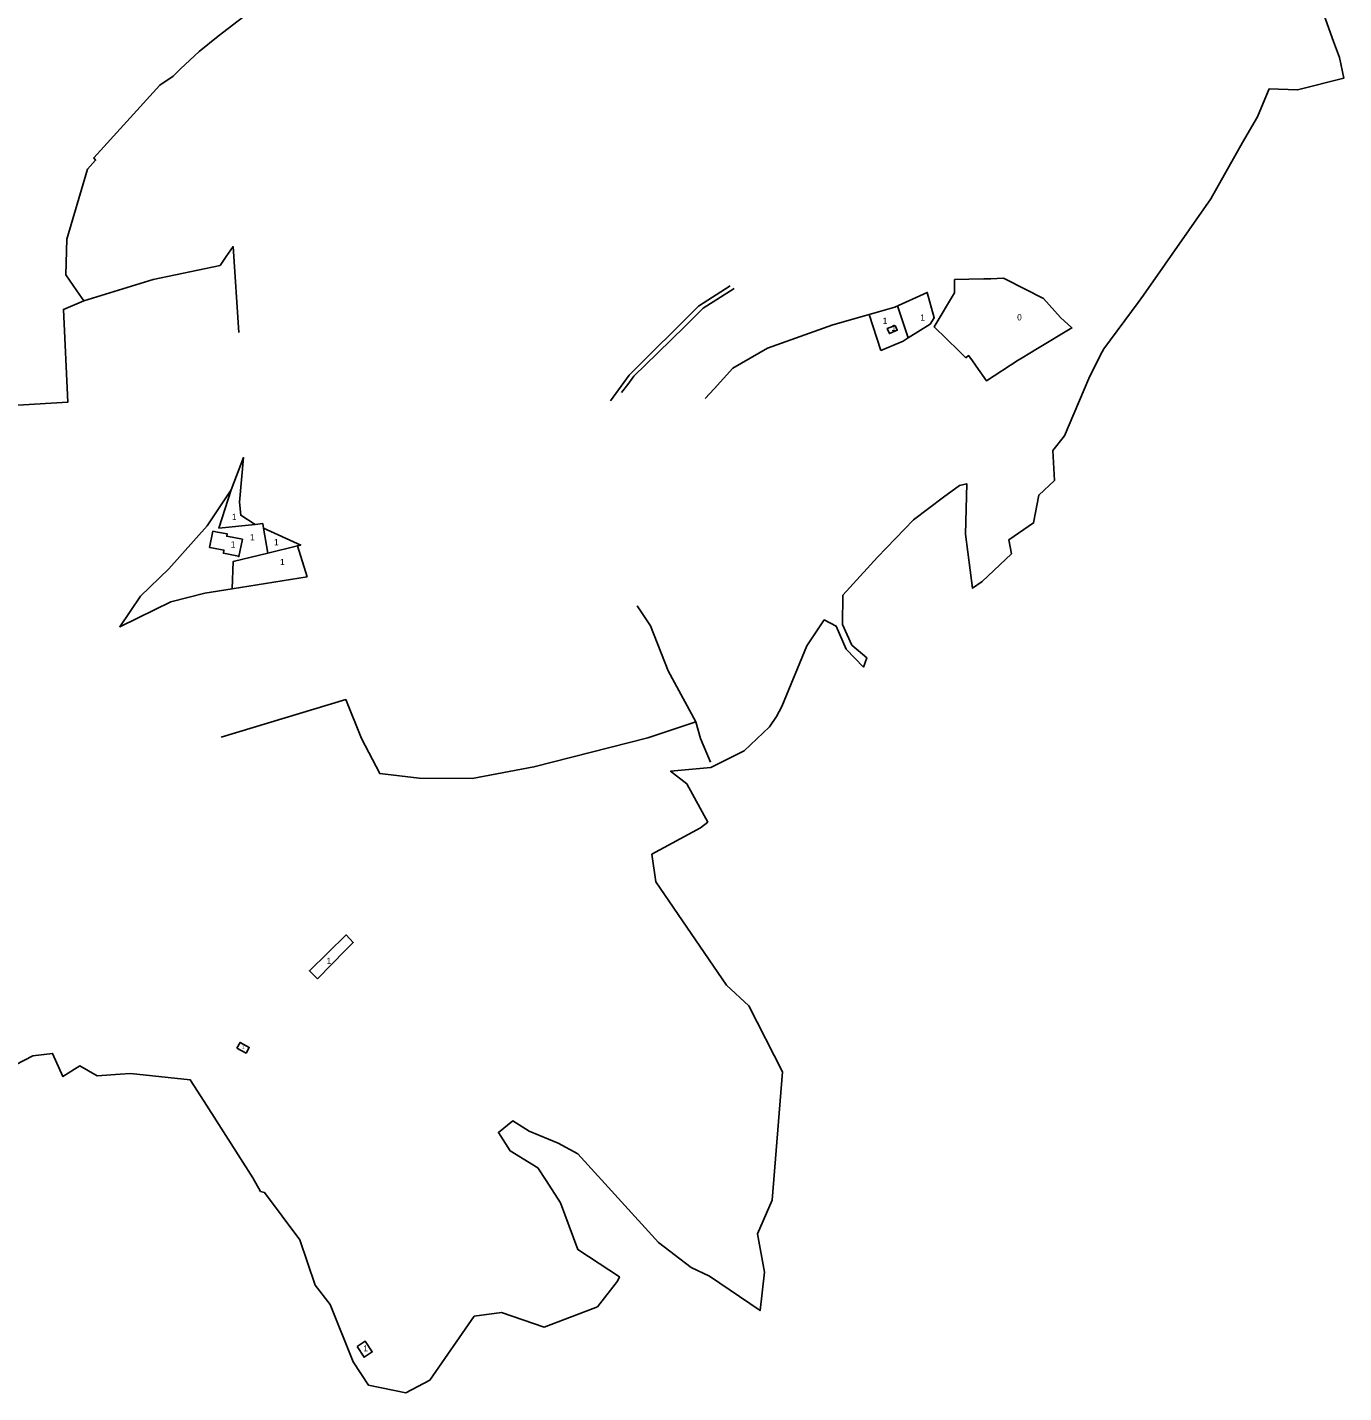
# Model space of a CAD drawing. Extents: x -494856 to -492815, y -1145343 to -1142968.
# Drawn here: x -494018 to -493180, y -1145025 to -1144155 of the extents above; entities that cross this region are included whole.
import ezdxf

# ---------------------------------------------------------------- set-up
doc = ezdxf.new("R2010")
doc.units = 0
for name, color, linetype in [('Level 255', 7, 'Continuous'), ('NERES_POP', 7, 'Continuous'), ('NERES_SET', 7, 'Continuous'), ('OVNE_POP', 7, 'Continuous'), ('OVNE_SET', 7, 'Continuous'), ('OVNI_SET', 7, 'Continuous'), ('POR_SET', 7, 'Continuous')]:
    doc.layers.add(name, color=color, linetype=linetype)

msp = doc.modelspace()

# ---------------------------------------------------------------- linework, layer by layer
at = {"layer": 'NERES_SET'}
for p, q in [((-493463.77, -1144332.66), (-493456.96, -1144353)), ((-493864.59, -1144489.99), (-493867.31, -1144474.24))]:
    msp.add_line(p, q, dxfattribs=at)
for points in [[(-493474.34, -1144361.13), (-493460.19, -1144355.01), (-493456.96, -1144353), (-493442.97, -1144344.29), (-493440.37, -1144340.24), (-493444.77, -1144324.08), (-493465.36, -1144333.38), (-493481.68, -1144338.07), (-493474.34, -1144361.13)], [(-493465.16, -1144345.03), (-493470.21, -1144347.11), (-493468.93, -1144350.26), (-493463.87, -1144348.17), (-493465.16, -1144345.03)], [(-493839.51, -1144505.25), (-493845.75, -1144485.41), (-493843.66, -1144484.9), (-493867.31, -1144474.24), (-493867.82, -1144471.29), (-493872.77, -1144471.82), (-493881.83, -1144465.91), (-493882.75, -1144457.66), (-493880.08, -1144429.23), (-493887.98, -1144449.69), (-493903.17, -1144472.68), (-493927.68, -1144500.06), (-493945.66, -1144517.42), (-493958.85, -1144536.9), (-493947.2, -1144531.21), (-493926.34, -1144521.03), (-493904.68, -1144515.59), (-493887.28, -1144512.83), (-493839.51, -1144505.25)], [(-493887.98, -1144449.69), (-493895.75, -1144474.27), (-493872.77, -1144471.82)], [(-493880.84, -1144481.11), (-493890.74, -1144479.29), (-493890.44, -1144477.86), (-493896.76, -1144476.63), (-493899.54, -1144476.09), (-493901.66, -1144486.4), (-493899.21, -1144486.86), (-493892.53, -1144488.11), (-493892.84, -1144490.14), (-493883.3, -1144491.99), (-493883.32, -1144492.24), (-493883.07, -1144492.28), (-493880.84, -1144481.11)], [(-493887.28, -1144512.83), (-493886.66, -1144495.37), (-493864.59, -1144489.99), (-493845.75, -1144485.41)], [(-493833.05, -1144761.18), (-493815.06, -1144742.79), (-493810.27, -1144737.9), (-493814.82, -1144733.12), (-493838.14, -1144755.98), (-493833.05, -1144761.18)], [(-493884.3, -1144805.21), (-493882.32, -1144801.59), (-493876.46, -1144804.8), (-493878.45, -1144808.42), (-493884.3, -1144805.21)], [(-493807.73, -1144995.25), (-493802.55, -1144991.88), (-493798.16, -1144998.63), (-493803.34, -1145002), (-493807.73, -1144995.25)]]:
    msp.add_lwpolyline(points, dxfattribs=at)
at = {"layer": 'OVNE_SET'}
for points in [[(-493391.26, -1144490.58), (-493392.81, -1144481.56), (-493377.07, -1144470.82), (-493373.77, -1144453.1), (-493363.72, -1144443.72), (-493364.89, -1144424.71), (-493357.31, -1144415.43), (-493342, -1144378.84), (-493334.48, -1144363.83), (-493332.27, -1144360.08), (-493310.53, -1144330.59), (-493307.09, -1144325.92), (-493264.2, -1144264.49), (-493244.07, -1144228.61), (-493234.47, -1144212.27), (-493232.98, -1144208.63), (-493227.2, -1144194.53), (-493208.99, -1144195.14), (-493179.67, -1144187.67), (-493182.31, -1144174.57), (-493186.18, -1144164.23), (-493200.41, -1144124.33)], [(-493877.18, -1144146.31), (-493896.2, -1144160.96), (-493908.35, -1144170.77), (-493920.3, -1144181.64), (-493922.82, -1144184.17), (-493924.92, -1144186.28), (-493933.37, -1144192.19), (-493975.39, -1144238.44), (-493974.24, -1144239.92), (-493979.36, -1144245.52), (-493992.48, -1144290.17), (-493993.27, -1144312.87), (-493986.15, -1144323.12), (-493981.79, -1144329.39), (-493994.7, -1144334.94), (-493991.9, -1144393.92), (-494126.29, -1144401.94)], [(-494025.28, -1144815.77), (-494014.28, -1144810.1), (-494001.7, -1144808.56), (-493995.06, -1144823.33), (-493984.26, -1144816.54), (-493973.23, -1144822.9), (-493958.68, -1144821.91), (-493952.03, -1144821.46), (-493913.99, -1144825.36), (-493905.1, -1144839.3), (-493874.16, -1144887.84), (-493869.23, -1144896.41), (-493866.63, -1144897.15), (-493844.28, -1144927.36), (-493834.46, -1144956.07), (-493824.92, -1144968.44), (-493810.2, -1145005.04), (-493800.47, -1145019.83), (-493776.76, -1145024.61), (-493761.56, -1145016.66), (-493733.22, -1144975.99), (-493715.89, -1144973.59), (-493709.06, -1144975.94), (-493688.67, -1144982.93), (-493654.74, -1144970.03), (-493642.02, -1144953.58), (-493640.81, -1144950.84), (-493667.28, -1144933.48), (-493678.27, -1144903.8), (-493687.35, -1144889.42), (-493692.79, -1144881.47), (-493710.23, -1144870.65), (-493717.8, -1144858.9), (-493708.61, -1144851.52), (-493698.31, -1144858.14), (-493679.79, -1144865.64), (-493667.32, -1144872.56), (-493615.82, -1144929.02), (-493595.09, -1144944.89), (-493583.38, -1144950.39), (-493551.22, -1144972.37), (-493548.51, -1144947.81), (-493552.96, -1144923.5), (-493543.6, -1144902.02), (-493536.9, -1144820.34), (-493558.41, -1144778.35), (-493572.68, -1144765.06), (-493617.52, -1144699.37), (-493620.13, -1144681.68), (-493589.17, -1144664.99), (-493584.49, -1144661.27), (-493597.81, -1144636.97), (-493608.17, -1144628.95), (-493582.62, -1144626.63), (-493561.44, -1144615.93), (-493545.19, -1144600.7), (-493540.78, -1144594.03), (-493537.34, -1144587.82), (-493521.42, -1144549.12), (-493510.35, -1144532.58), (-493502.68, -1144536.5), (-493496.46, -1144551.15), (-493485.41, -1144562.58), (-493483.33, -1144556.66), (-493492.87, -1144548.65), (-493498.78, -1144535.49), (-493498.53, -1144516.78), (-493476.41, -1144492.57), (-493453.56, -1144468.76), (-493434.4, -1144454.46), (-493424.3, -1144446.92)], [(-493424.3, -1144446.92), (-493419.69, -1144445.89), (-493420.39, -1144477.98), (-493416.08, -1144512.29), (-493409.91, -1144508.07), (-493391.26, -1144490.58)]]:
    msp.add_lwpolyline(points, dxfattribs=at)
at = {"layer": 'OVNI_SET'}
msp.add_lwpolyline([(-493427.45, -1144315.87), (-493427.44, -1144324.29), (-493440.48, -1144346.07), (-493424.77, -1144361.31), (-493420.27, -1144365.67), (-493418.49, -1144364.31), (-493416.44, -1144367.08), (-493413.62, -1144370.97), (-493407.07, -1144380.45), (-493386.95, -1144367.31), (-493384.27, -1144365.66), (-493374.56, -1144359.77), (-493352.68, -1144346.72), (-493359.86, -1144339.98), (-493370.83, -1144327.89), (-493395.02, -1144315.68), (-493396.31, -1144315.03), (-493400.38, -1144315.19), (-493404.24, -1144315.35), (-493408.68, -1144315.46), (-493418.29, -1144315.69), (-493427.45, -1144315.87)], dxfattribs=at)
at = {"layer": 'POR_SET'}
for points in [[(-493883.18, -1144349.61), (-493886.74, -1144294.91), (-493891.07, -1144301.17)], [(-493981.79, -1144329.39), (-493937.68, -1144315.8), (-493895.05, -1144306.93), (-493891.07, -1144301.17)], [(-493646.45, -1144393.19), (-493634.56, -1144376.68), (-493590.51, -1144332.9), (-493570.17, -1144319.8)], [(-493567.8, -1144321.52), (-493587.4, -1144334.19), (-493598.97, -1144345.5), (-493616.55, -1144362.69), (-493631.63, -1144377.43), (-493635.52, -1144382.6), (-493639.39, -1144387.76)], [(-493481.68, -1144338.07), (-493484.68, -1144338.93), (-493504.9, -1144344.75), (-493546.52, -1144359.6), (-493568.61, -1144372.37), (-493580.56, -1144385.46), (-493586.22, -1144391.66)], [(-493894.26, -1144607.28), (-493814.96, -1144583.26), (-493805.03, -1144608.19), (-493793.38, -1144630.42), (-493768.29, -1144633.3), (-493734.57, -1144633.63), (-493695.2, -1144626.18), (-493622.69, -1144607.7), (-493592.17, -1144597.43), (-493609.77, -1144564.99), (-493621.07, -1144536.32), (-493629.49, -1144523.7)], [(-493582.88, -1144623.14), (-493589.14, -1144608.02), (-493592.17, -1144597.43)]]:
    msp.add_lwpolyline(points, dxfattribs=at)

# ---------------------------------------------------------------- texts
at = {"layer": 'Level 255'}
for height, p in [(4, (-493827.2, -1144751.7)), (2, (-493881.05, -1144805.55)), (4, (-493803.87, -1144998.36))]:
    msp.add_text('1', height=height, dxfattribs=at).set_placement(p)
at = {"layer": 'NERES_POP'}
for p in [(-493449.24, -1144342.01), (-493473.19, -1144344.13), (-493467.58, -1144348.53), (-493887.5, -1144468.97), (-493876.01, -1144481.95), (-493888.23, -1144486.52), (-493860.69, -1144485.04), (-493856.86, -1144497.72)]:
    msp.add_text('1', height=4, dxfattribs=at).set_placement(p)
at = {"layer": 'OVNE_POP'}
msp.add_text('0', height=4, dxfattribs=at).set_placement((-493387.59, -1144341.91))

doc.saveas('drawing.dxf')
